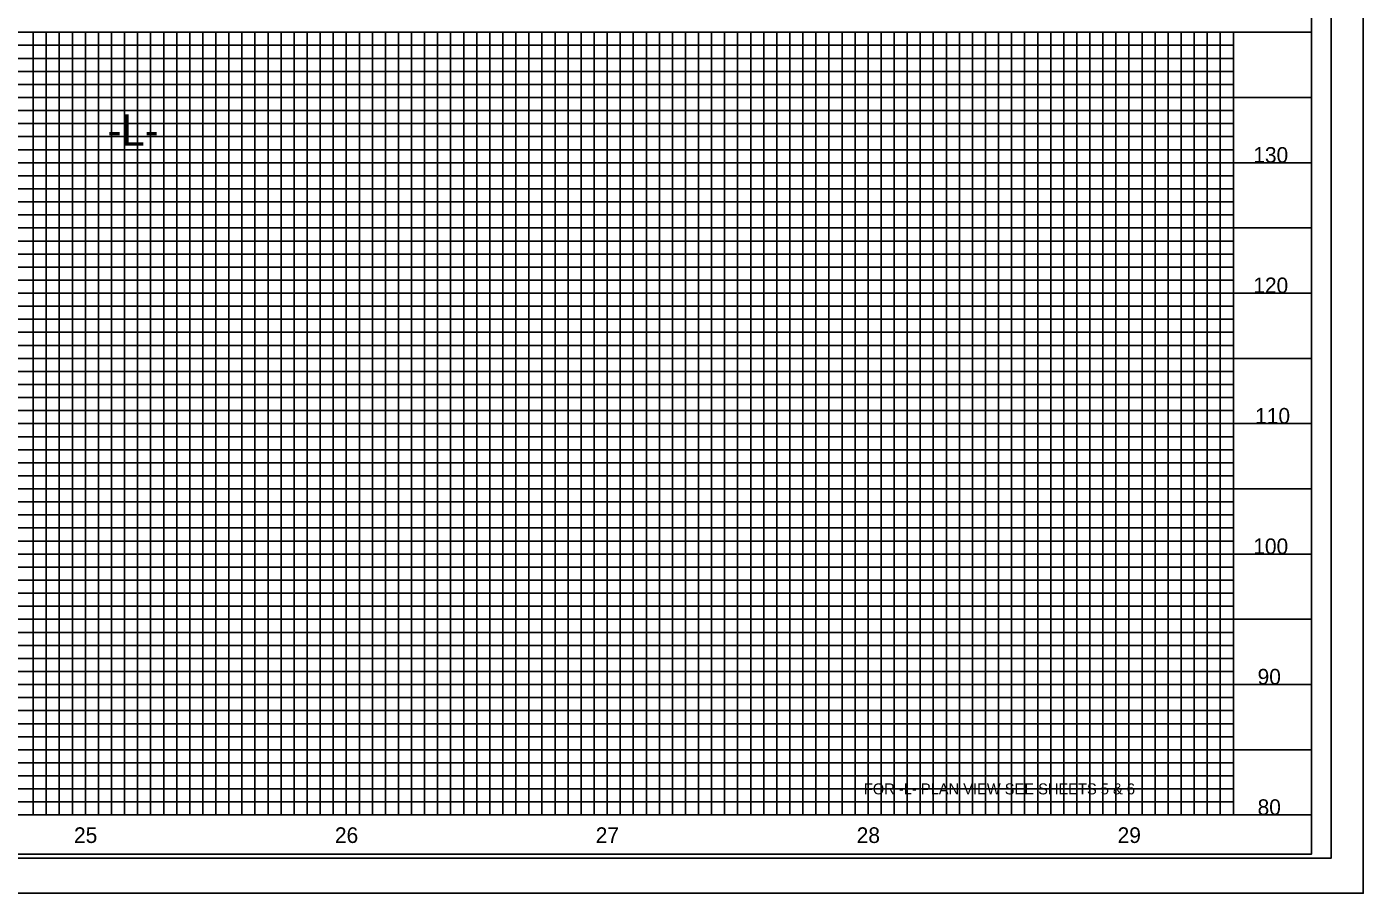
# Model space of a CAD drawing. Extents: x 2113883 to 2114903, y 714180 to 714840.
# Drawn here: x 2114390 to 2114903, y 714180 to 714512 of the extents above; entities that cross this region are included whole.
import ezdxf

# ---------------------------------------------------------------- set-up
doc = ezdxf.new("R2010")
doc.units = 0
for name, color, linetype in [('Exist Vertical Profile Horizontal Axis Label Major', 7, 'Continuous'), ('Exist Vertical Profile Vertical Axis Label', 7, 'Continuous'), ('Prop Grid Mask', 7, 'Continuous'), ('Prop PFL Text', 7, 'Continuous'), ('Sheet Cutting Line CELL', 7, 'Continuous'), ('Sheet Layout Profile Border Port 2', 7, 'Continuous'), ('Sheet Plot Border Inside CELL', 7, 'Continuous'), ('Sheet Plot Border Outside CELL', 7, 'Continuous'), ('Sheet Profile CELL', 7, 'Continuous'), ('Sheet Profile Grid Major CELL', 7, 'Continuous'), ('Sheet Profile Grid Middle CELL', 7, 'Continuous'), ('Sheet Profile Grid Minor CELL', 7, 'Continuous')]:
    doc.layers.add(name, color=color, linetype=linetype)

msp = doc.modelspace()

# ---------------------------------------------------------------- linework, layer by layer
at = {"layer": 'Exist Vertical Profile Vertical Axis Label'}
msp.add_lwpolyline([(2114702.76, 714225.29), (2114847.76, 714225.29), (2114847.76, 714215.29), (2114702.76, 714215.29)], close=True, dxfattribs=at)
at = {"layer": 'Prop Grid Mask'}
for points in [[(2114412.76, 714460.29), (2114452.76, 714460.29), (2114452.76, 714485.29), (2114412.76, 714485.29)], [(2114702.76, 714225.29), (2114847.76, 714225.29), (2114847.76, 714215.29), (2114702.76, 714215.29)]]:
    msp.add_lwpolyline(points, close=True, dxfattribs=at)
at = {"layer": 'Prop PFL Text'}
msp.add_lwpolyline([(2114412.76, 714460.29), (2114452.76, 714460.29), (2114452.76, 714485.29), (2114412.76, 714485.29)], close=True, dxfattribs=at)
at = {"layer": 'Sheet Cutting Line CELL'}
for p, q in [((2114902.56, 714180.29), (2114902.56, 714840.29)), ((2113882.56, 714180.29), (2114902.56, 714180.29))]:
    msp.add_line(p, q, dxfattribs=at)
at = {"layer": 'Sheet Layout Profile Border Port 2'}
msp.add_lwpolyline([(2114012.76, 714510.29), (2114852.76, 714510.29), (2114852.76, 714210.29), (2114012.76, 714210.29)], close=True, dxfattribs=at)
at = {"layer": 'Sheet Plot Border Inside CELL'}
msp.add_lwpolyline([(2113890.36, 714193.76), (2114890.26, 714193.76), (2114890.26, 714826.82), (2113890.36, 714826.82)], close=True, dxfattribs=at)
at = {"layer": 'Sheet Plot Border Outside CELL'}
msp.add_lwpolyline([(2113882.56, 714180.29), (2114902.56, 714180.29), (2114902.56, 714840.29), (2113882.56, 714840.29)], close=True, dxfattribs=at)
at = {"layer": 'Sheet Profile CELL'}
for p, q in [((2113982.76, 714510.29), (2114882.76, 714510.29)), ((2114882.76, 714210.29), (2113982.76, 714210.29)), ((2113982.76, 714195.29), (2114882.76, 714195.29))]:
    msp.add_line(p, q, dxfattribs=at)
msp.add_lwpolyline([(2114882.76, 714825.29), (2113982.76, 714825.29), (2113982.76, 714195.29), (2114882.76, 714195.29)], close=True, dxfattribs=at)
at = {"layer": 'Sheet Profile Grid Major CELL'}
for p, q in [((2114412.76, 714510.29), (2114412.76, 714210.29)), ((2114437.76, 714510.29), (2114437.76, 714210.29)), ((2114462.76, 714510.29), (2114462.76, 714210.29)), ((2114487.76, 714510.29), (2114487.76, 714210.29)), ((2114512.76, 714510.29), (2114512.76, 714210.29)), ((2114537.76, 714510.29), (2114537.76, 714210.29)), ((2114562.76, 714510.29), (2114562.76, 714210.29)), ((2114587.76, 714510.29), (2114587.76, 714210.29)), ((2114612.76, 714510.29), (2114612.76, 714210.29)), ((2114637.76, 714510.29), (2114637.76, 714210.29)), ((2114662.76, 714510.29), (2114662.76, 714210.29)), ((2114687.76, 714510.29), (2114687.76, 714210.29)), ((2114712.76, 714510.29), (2114712.76, 714210.29)), ((2114737.76, 714510.29), (2114737.76, 714210.29)), ((2114762.76, 714510.29), (2114762.76, 714210.29)), ((2114787.76, 714510.29), (2114787.76, 714210.29)), ((2114812.76, 714510.29), (2114812.76, 714210.29)), ((2114837.76, 714510.29), (2114837.76, 714210.29)), ((2114852.76, 714510.29), (2114852.76, 714210.29)), ((2113982.76, 714485.29), (2114882.76, 714485.29)), ((2114882.76, 714460.29), (2113982.76, 714460.29)), ((2113982.76, 714435.29), (2114882.76, 714435.29)), ((2114882.76, 714410.29), (2113982.76, 714410.29)), ((2113982.76, 714385.29), (2114882.76, 714385.29)), ((2114882.76, 714360.29), (2113982.76, 714360.29)), ((2113982.76, 714335.29), (2114882.76, 714335.29)), ((2114882.76, 714310.29), (2113982.76, 714310.29)), ((2113982.76, 714285.29), (2114882.76, 714285.29)), ((2114882.76, 714260.29), (2113982.76, 714260.29)), ((2113982.76, 714235.29), (2114882.76, 714235.29))]:
    msp.add_line(p, q, dxfattribs=at)
at = {"layer": 'Sheet Profile Grid Middle CELL'}
for p, q in [((2114012.76, 714505.29), (2114852.76, 714505.29)), ((2114012.76, 714500.29), (2114852.76, 714500.29)), ((2114012.76, 714495.29), (2114852.76, 714495.29)), ((2114012.76, 714490.29), (2114852.76, 714490.29)), ((2114012.76, 714480.29), (2114852.76, 714480.29)), ((2114012.76, 714475.29), (2114852.76, 714475.29)), ((2114012.76, 714470.29), (2114852.76, 714470.29)), ((2114012.76, 714465.29), (2114852.76, 714465.29)), ((2114012.76, 714455.29), (2114852.76, 714455.29)), ((2114012.76, 714450.29), (2114852.76, 714450.29)), ((2114012.76, 714445.29), (2114852.76, 714445.29)), ((2114012.76, 714440.29), (2114852.76, 714440.29)), ((2114012.76, 714430.29), (2114852.76, 714430.29)), ((2114012.76, 714425.29), (2114852.76, 714425.29)), ((2114012.76, 714420.29), (2114852.76, 714420.29)), ((2114012.76, 714415.29), (2114852.76, 714415.29)), ((2114012.76, 714405.29), (2114852.76, 714405.29)), ((2114012.76, 714400.29), (2114852.76, 714400.29)), ((2114012.76, 714395.29), (2114852.76, 714395.29)), ((2114012.76, 714390.29), (2114852.76, 714390.29)), ((2114012.76, 714380.29), (2114852.76, 714380.29)), ((2114012.76, 714375.29), (2114852.76, 714375.29)), ((2114012.76, 714370.29), (2114852.76, 714370.29)), ((2114012.76, 714365.29), (2114852.76, 714365.29)), ((2114012.76, 714355.29), (2114852.76, 714355.29)), ((2114012.76, 714350.29), (2114852.76, 714350.29)), ((2114012.76, 714345.29), (2114852.76, 714345.29)), ((2114012.76, 714340.29), (2114852.76, 714340.29)), ((2114012.76, 714330.29), (2114852.76, 714330.29)), ((2114012.76, 714325.29), (2114852.76, 714325.29)), ((2114012.76, 714320.29), (2114852.76, 714320.29)), ((2114012.76, 714315.29), (2114852.76, 714315.29)), ((2114012.76, 714305.29), (2114852.76, 714305.29)), ((2114012.76, 714300.29), (2114852.76, 714300.29)), ((2114012.76, 714295.29), (2114852.76, 714295.29)), ((2114012.76, 714290.29), (2114852.76, 714290.29)), ((2114012.76, 714280.29), (2114852.76, 714280.29)), ((2114012.76, 714275.29), (2114852.76, 714275.29)), ((2114012.76, 714270.29), (2114852.76, 714270.29)), ((2114012.76, 714265.29), (2114852.76, 714265.29)), ((2114012.76, 714255.29), (2114852.76, 714255.29)), ((2114012.76, 714250.29), (2114852.76, 714250.29)), ((2114012.76, 714245.29), (2114852.76, 714245.29)), ((2114012.76, 714240.29), (2114852.76, 714240.29)), ((2114012.76, 714230.29), (2114852.76, 714230.29)), ((2114012.76, 714225.29), (2114852.76, 714225.29)), ((2114012.76, 714220.29), (2114852.76, 714220.29)), ((2114012.76, 714215.29), (2114852.76, 714215.29))]:
    msp.add_line(p, q, dxfattribs=at)
msp.add_lwpolyline([(2114777.76, 714375.29), (2114852.76, 714375.29)], dxfattribs=at)
at = {"layer": 'Sheet Profile Grid Minor CELL'}
for p, q in [((2114392.76, 714510.29), (2114392.76, 714210.29)), ((2114397.76, 714510.29), (2114397.76, 714210.29)), ((2114402.76, 714510.29), (2114402.76, 714210.29)), ((2114407.76, 714510.29), (2114407.76, 714210.29)), ((2114417.76, 714510.29), (2114417.76, 714210.29)), ((2114422.76, 714510.29), (2114422.76, 714210.29)), ((2114427.76, 714510.29), (2114427.76, 714210.29)), ((2114432.76, 714510.29), (2114432.76, 714210.29)), ((2114442.76, 714510.29), (2114442.76, 714210.29)), ((2114447.76, 714510.29), (2114447.76, 714210.29)), ((2114452.76, 714510.29), (2114452.76, 714210.29)), ((2114457.76, 714510.29), (2114457.76, 714210.29)), ((2114467.76, 714510.29), (2114467.76, 714210.29)), ((2114472.76, 714510.29), (2114472.76, 714210.29)), ((2114477.76, 714510.29), (2114477.76, 714210.29)), ((2114482.76, 714510.29), (2114482.76, 714210.29)), ((2114492.76, 714510.29), (2114492.76, 714210.29)), ((2114497.76, 714510.29), (2114497.76, 714210.29)), ((2114502.76, 714510.29), (2114502.76, 714210.29)), ((2114507.76, 714510.29), (2114507.76, 714210.29)), ((2114517.76, 714510.29), (2114517.76, 714210.29)), ((2114522.76, 714510.29), (2114522.76, 714210.29)), ((2114527.76, 714510.29), (2114527.76, 714210.29)), ((2114532.76, 714510.29), (2114532.76, 714210.29)), ((2114542.76, 714510.29), (2114542.76, 714210.29)), ((2114547.76, 714510.29), (2114547.76, 714210.29)), ((2114552.76, 714510.29), (2114552.76, 714210.29)), ((2114557.76, 714510.29), (2114557.76, 714210.29)), ((2114567.76, 714510.29), (2114567.76, 714210.29)), ((2114572.76, 714510.29), (2114572.76, 714210.29)), ((2114577.76, 714510.29), (2114577.76, 714210.29)), ((2114582.76, 714510.29), (2114582.76, 714210.29)), ((2114592.76, 714510.29), (2114592.76, 714210.29)), ((2114597.76, 714510.29), (2114597.76, 714210.29)), ((2114602.76, 714510.29), (2114602.76, 714210.29)), ((2114607.76, 714510.29), (2114607.76, 714210.29)), ((2114617.76, 714510.29), (2114617.76, 714210.29)), ((2114622.76, 714510.29), (2114622.76, 714210.29)), ((2114627.76, 714510.29), (2114627.76, 714210.29)), ((2114632.76, 714510.29), (2114632.76, 714210.29)), ((2114642.76, 714510.29), (2114642.76, 714210.29)), ((2114647.76, 714510.29), (2114647.76, 714210.29)), ((2114652.76, 714510.29), (2114652.76, 714210.29)), ((2114657.76, 714510.29), (2114657.76, 714210.29)), ((2114667.76, 714510.29), (2114667.76, 714210.29)), ((2114672.76, 714510.29), (2114672.76, 714210.29)), ((2114677.76, 714510.29), (2114677.76, 714210.29)), ((2114682.76, 714510.29), (2114682.76, 714210.29)), ((2114692.76, 714510.29), (2114692.76, 714210.29)), ((2114697.76, 714510.29), (2114697.76, 714210.29)), ((2114702.76, 714510.29), (2114702.76, 714210.29)), ((2114707.76, 714510.29), (2114707.76, 714210.29)), ((2114717.76, 714510.29), (2114717.76, 714210.29)), ((2114722.76, 714510.29), (2114722.76, 714210.29)), ((2114727.76, 714510.29), (2114727.76, 714210.29)), ((2114732.76, 714510.29), (2114732.76, 714210.29)), ((2114742.76, 714510.29), (2114742.76, 714210.29)), ((2114747.76, 714510.29), (2114747.76, 714210.29)), ((2114752.76, 714510.29), (2114752.76, 714210.29)), ((2114757.76, 714510.29), (2114757.76, 714210.29)), ((2114767.76, 714510.29), (2114767.76, 714210.29)), ((2114772.76, 714510.29), (2114772.76, 714210.29)), ((2114777.76, 714510.29), (2114777.76, 714210.29)), ((2114782.76, 714510.29), (2114782.76, 714210.29)), ((2114792.76, 714510.29), (2114792.76, 714210.29)), ((2114797.76, 714510.29), (2114797.76, 714210.29)), ((2114802.76, 714510.29), (2114802.76, 714210.29)), ((2114807.76, 714510.29), (2114807.76, 714210.29)), ((2114817.76, 714510.29), (2114817.76, 714210.29)), ((2114822.76, 714510.29), (2114822.76, 714210.29)), ((2114827.76, 714510.29), (2114827.76, 714210.29)), ((2114832.76, 714510.29), (2114832.76, 714210.29)), ((2114842.76, 714510.29), (2114842.76, 714210.29)), ((2114847.76, 714510.29), (2114847.76, 714210.29))]:
    msp.add_line(p, q, dxfattribs=at)

# ---------------------------------------------------------------- texts
at = {"layer": 'Exist Vertical Profile Horizontal Axis Label Major'}
for s, p in [('25', (2114408.39, 714199.56)), ('25', (2114408.39, 714199.56)), ('25', (2114408.39, 714199.56)), ('25', (2114408.39, 714199.56)), ('26', (2114508.4, 714199.56)), ('26', (2114508.4, 714199.56)), ('26', (2114508.4, 714199.56)), ('26', (2114508.4, 714199.56)), ('27', (2114608.36, 714199.56)), ('27', (2114608.36, 714199.56)), ('27', (2114608.36, 714199.56)), ('27', (2114608.36, 714199.56)), ('28', (2114708.39, 714199.56)), ('28', (2114708.39, 714199.56)), ('28', (2114708.39, 714199.56)), ('28', (2114708.39, 714199.56)), ('29', (2114808.4, 714199.56))]:
    msp.add_text(s, height=6, dxfattribs=at).set_placement(p)
at = {"layer": 'Exist Vertical Profile Vertical Axis Label'}
for s, p in [('130', (2114860.4, 714460.29)), ('120', (2114860.4, 714410.29)), ('110', (2114861.12, 714360.29)), ('100', (2114860.4, 714310.29)), ('90', (2114862.06, 714260.29)), ('80', (2114862.06, 714210.29))]:
    msp.add_text(s, height=6, dxfattribs=at).set_placement(p)
at = {"layer": 'Prop PFL Text'}
for s, height, p in [('-L-', 12, (2114421.22, 714466.79)), ('FOR -L- PLAN VIEW SEE SHEETS 5 & 6', 4.2, (2114711.15, 714218.19))]:
    msp.add_text(s, height=height, dxfattribs=at).set_placement(p)

doc.saveas('drawing.dxf')
